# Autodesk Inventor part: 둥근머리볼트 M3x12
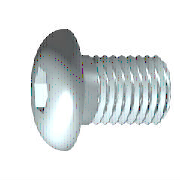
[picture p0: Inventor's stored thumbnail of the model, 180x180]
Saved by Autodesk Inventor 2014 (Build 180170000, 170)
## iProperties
IsCustomPart: 0
Created: 2012-02
Part Number: 둥근머리볼트 M3x12
Material: 강철
Description: 6각 소켓 버튼 머리 나사 - 제품 등급 A
Document SubType Name: Modeling
Standard: ISO 7380
Designer: mduedu
Standard Revision: Third edition 2004-01-15
Standards Organization: ISO
Language: ko-KR
Size Designation: M3 x 12
Categories: <MemberInstance><Categories><Category DisplayName="조임쇠" InternalName="e4da775c-781d-43d5-af7c-5136215cf5a6" Mnemonic="FSTN"><Category DisplayName="볼트" InternalN
Density: 7.85 g/cm^3
Appearance: 강철
Author: mduedu
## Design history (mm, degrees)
sketch "스케치1"
  geometry: L1 (0.057, 0)-(12, 0); L2 (12, 0)-(12, 1.5); L3 (12, 1.5)-(1, 1.5); L4 (1, 1.5)-(0.693, 1.5); L5 (0.693, 1.5)-(0, 1.5); L6 (0, 1.5)-(0, 2.85); L7 (0, 2.85)-(-1.65, 2.85); L8 (-1.65, 2.85)-(-1.65, 1.155); L9 (-1.65, 1.155)-(-0.61, 1.155); L10 (-0.61, 1.155)-(0.057, 0); L11 (-4.38, 0)-(14.73, 0) reference; L12 (0, -0.57)-(0, 3.42) reference; L13 (1, 1.5)-(0, 1.5)
  constraints: 22 end point, 6 parallel, 2 collinear, 2 perpendicular, 1 horizontal, 1 point on line
  dimensions: "d1" = 11 distance from line of L3.end L2 (= GEL); "d2" = 0.30683 distance of L4.end L3.end (computed from GAL); "d3" = 1.65 distance between parallel lines of L8 L6 (= KOH); "d4" = 1.04 distance of L8.end L9.end (= INTI); "d5" = 60 deg angle of L10 L1; "d6" = 3 diameter of L3 L1 (= GD); "d7" = 3 diameter of L5 L1 (= BDM); "d8" = 2.3094 diameter of L9 L1 (= 1.1547 x SW); "d9" = 5.7 diameter of L7 L1 (= KOD); "d26" = 12 distance between parallel lines of L12 L2 (= NLG)
revolve "본체" sketch "스케치1" stored, may be unused: angle "d10" = 90 deg
sketch "스케치2"
  geometry: L1 (0, -3.99)-(0, 3.99) reference; L2 (-3.99, 0)-(3.99, 0) reference; L3 (1.155, 0)-(0.577, -1); L4 (0.577, -1)-(-0.577, -1); L5 (-0.577, -1)-(-1.155, 0); L6 (-1.155, 0)-(-0.577, 1); L7 (-0.577, 1)-(0.577, 1); L8 (0.577, 1)-(1.155, 0); 2 further points
  constraints: 12 end point, 1 coincident, 1 horizontal alignment, 1 point on line, 12 other
extrude "슬롯" join sketch "스케치2" stored distance "d11" = 10; taper "d12" = 0 deg
workplane "Work Plane1"
body "Solid1"
fillet "모깎기1" dims "d17" = 1.45 (= RR)
feature "스레드" dims "d13" = 11 (= GEL), "d14" = 0
chamfer "모따기1" distance "d15" = 0.30673 (= -0.5 x SPD + 0.5 x GD); stored, may be unused: second distance "d16" = 0.30673 (= GUL), angle "d27" = 45 deg
fillet "모깎기2" dims "d30" = 0.1 (= R)
other parameters: "GD" = 3 (= NND) [user parameter; used in 2 equation terms], "NLG" = 12 [user parameter; used in 1 equation term], "GEL" = 11 [user parameter; used in 2 equation terms], "KOD" = 5.7 [user parameter; used in 1 equation term], "KOH" = 1.65 [user parameter; used in 1 equation term], "INTI" = 1.04 [user parameter; used in 1 equation term], "GAL" = 0.30673 (= 0.61345 x PTC) [user parameter; used in 1 equation term], "GUL" = 0.30673 (= 0.61345 x PTC) [user parameter; used in 1 equation term], "BDM" = 3 (= NND) [user parameter; used in 1 equation term], "SW" = 2 [user parameter; used in 1 equation term], "RR" = 1.45 [user parameter; used in 1 equation term], "SPD" = 2.38655 (= NND - 1.2269 x PTC) [user parameter; used in 1 equation term], "d19" = 0, "d28" = 0, "d29" = 0, "R" = 0.1 [user parameter; used in 1 equation term], "TOA" = 30 deg [user parameter], "GD1" = 2.38655 (= THREADDIA - 1.2269 x PTC) [user parameter], "THREADDIA" = 3 [user parameter; used in 1 equation term], "PTC" = 0.5 [user parameter; used in 5 equation terms], "NND" = 3 [user parameter; used in 3 equation terms], "KOH1" = 0.2 [user parameter], "E0" = 2.31 [user parameter]
